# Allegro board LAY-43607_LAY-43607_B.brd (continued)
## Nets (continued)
GND: BH9.1 BH10.1 BT3.3 C5.2 C12.2 C14.2 C18.1 C20.2 C21.2 C22.2 C24.2 C25.2 C26.2 C27.2 C28.2 C30.2 C31.2 C32.2 C113.2 C114.2 C115.2 C116.2 C118.2 C119.2 C120.2 C125.2 C148.2 C149.2 C151.2 C152.2 C153.2 C155.2 C156.2 C157.2 C159.2 C160.2 C161.2 C162.2 C163.2 C164.2 C165.2 C166.2 C167.2 C168.2 C169.2 C170.2 C171.2 C172.2 C173.2 C174.2 C175.2 C176.2 C180.2 C181.2 C182.2 C183.2 C184.2 C185.2 C186.2 C187.2 C188.2 C189.2 C190.2 C191.2 C193.2 C194.2 C195.2 C196.2 C197.2 C198.2 C199.2 C200.2 C201.2 C202.2 C203.2 C204.2 C205.2 C206.2 C207.2 C208.2 C209.2 C210.2 C211.2 C212.2 C213.2 C214.2 C215.2 C216.2 C217.2 C218.2 C219.2 C220.2 C221.2 C222.2 C223.2 C224.2 C225.2 C226.2 C227.2 C228.2 C229.2 C230.2 C231.2 C232.2 C233.2 C234.2 C235.2 C236.2 C237.2 C238.2 C239.2 C240.2 C241.2 C242.2 C243.2 C244.2 C245.2 C246.2 C247.2 C248.2 C249.2 C252.2 C254.2 C258.2 C259.2 C260.2 C261.2 C262.2 C263.2 C264.2 C265.2 C266.2 C267.2 C268.2 C269.2 C270.2 C271.2 C275.2 C277.2 C278.2 C279.2 C280.2 C281.2 C282.2 C283.2 C284.2 C285.2 C286.2 C287.2 C288.2 C289.2 C290.2 C291.2 C292.2 C293.2 C294.2 C295.2 C296.2 C297.2 C298.2 C299.2 C300.2 C301.2 C302.2 C303.2 C304.2 C305.2 C306.2 C307.2 C308.2 C309.2 C310.2 C311.2 C312.2 C313.2 C314.2 C315.2 C316.2 C317.2 C318.2 C319.2 C320.2 C321.2 C322.2 C323.2 C324.2 C328.2 C329.2 C330.2 C332.2 C333.2 C334.2 C336.2 C337.2 C338.2 C364.2 C365.2 C366.2 C367.2 C369.2 C374.2 C375.2 C383.2 C384.2 C386.2 C388.2 C438.2 C449.2 C450.2 C451.2 C452.2 C453.2 C454.2 C457.2 C458.2 C459.2 C460.2 C487.2 C488.2 C489.2 C492.2 C493.2 C497.2 C498.2 C517.2 C518.2 C519.2 C520.2 C521.2 C522.2 C523.2 C524.2 C668.2 C669.2 C693.2 C729.2 C772.2 C787.2 C788.2 C789.2 C798.2 C851.2 C852.2 C853.2 C854.2 C855.2 C905.2 C933.2 C934.2 C935.2 C936.2 C1000.2 C1001.2 C1003.2 C1004.2 C1005.2 C1007.2 C1008.2 C1009.2 C1010.2 C1011.2 C1013.2 C1015.2 C1016.2 C1017.2 C1018.2 C1019.2 C1020.2 C1021.2 C1022.2 C1023.2 C1024.1 C1103.2 C1104.2 C1139.2 C1140.2 C1141.2 C1142.2 C1143.1 C1144.1 C1145.1 C1146.1 C1147.1 C1148.1 C1149.1 C1150.2 C1151.2 C1152.2 C1153.2 C1154.2 C1155.2 C1156.2 C1157.2 C1174.2 C1248.2 C1249.2 C1251.2 C1253.2 C1255.2 C1256.2 C1258.2 C1259.2 C1271.2 C1272.2 C1273.2 C1274.2 C1275.2 C1276.2 C1277.2 C1278.2 C1280.2 C1282.2 C1283.2 C1295.2 C1296.2 C1297.2 C1298.2 C1299.2 C1302.2 C1304.2 C1305.2 C1306.2 C1307.2 C1308.2 C1309.2 C1310.2 C1313.2 C1314.2 C1315.2 C1316.2 C1317.2 C1318.2 C1319.2 C1320.2 C1321.2 C1322.2 C1323.2 C1324.2 C1327.2 C1328.2 C1329.2 C1330.2 C1331.2 C1332.2 C1333.1 C1334.2 C1337.2 C1338.2 C1339.2 C1340.2 C1342.1 C1343.2 C1344.2 C1345.2 C1346.2 C1347.2 C1348.2 C1349.2 C1350.2 C1351.2 C1361.2 C1362.2 C1363.2 C1364.2 C1365.2 C1366.2 C1367.2 C1368.2 C1369.2 C1370.2 C1371.2 C1372.2 C1373.2 C1374.2 C1375.2 C1376.2 C1377.2 C1378.2 C1379.2 C1380.2 C1382.2 C1384.2 C1385.2 C1386.2 C1387.2 C1388.2 C1389.2 C1390.2 C1391.2 C1392.2 C1393.2 C1394.2 C1395.2 C1396.2 C1397.2 C1398.2 C1399.2 C1400.2 C1401.2 C1402.2 C1403.2 C1404.2 C1406.2 C1408.2 C1409.2 C1410.2 C1411.2 C1412.2 C1413.2 C1414.2 C1415.2 C1416.2 C1417.2 C1418.2 C1419.2 C1420.2 C1421.2 C1422.2 C1423.2 C1424.2 C1425.2 C1426.2 C1427.2 C1428.2 C1430.2 C1432.2 C1433.2 C1434.2 C1435.2 C1436.2 C1437.2 C1438.2 C1439.2 C1440.2 C1441.2 C1442.2 C1443.2 C1444.2 C1445.2 C1446.2 C1447.2 C1448.2 C1449.2 C1450.2 C1451.2 C1452.2 C1453.2 C1454.2 C1455.2 C1456.2 C1457.2 C1458.2 C1459.2 C1460.2 C1461.2 C1462.2 C1463.2 C1464.2 C1465.2 C1466.2 C1467.2 C1468.2 C1469.2 C1470.2 C1471.2 C1475.2 C1476.2 C1481.2 C1489.2 C1490.2 C1491.2 C1492.2 C1493.2 C1494.2 C1495.2 C1520.2 C1521.2 C1523.2 C1524.2 C1525.2 C1526.2 C1530.2 C1531.2 C1532.2 C1533.2 C1534.2 C1535.2 C1536.2 C1537.2 C1538.2 C1540.2 C1542.2 C1544.2 C1545.2 C1546.2 C1547.2 C1548.2 C1549.2 C1550.2 C1551.2 C1552.2 C1553.2 C1554.2 C1555.2 C1556.2 C1557.2 C1558.2 C1559.2 C1560.2 C1561.2 C1562.2 C1563.2 C1564.2 C1565.2 C1566.2 C1567.2 C1568.2 C1569.2 C1570.2 C1571.2 C1572.2 C1573.2 C1574.2 C1575.2 C1577.2 C1579.2 C1581.2 C1584.2 C1585.2 C1586.2 C1587.2 D4.C(CATHODE) D508.C(CATHODE) FL2.2A FL2.2B FL3.2 FL4.2 FL5.2 FL7.2 FL8.2 FL18.2 FL19.2 FL22.2 FL28.2 FL29.2 FL30.2 FL31.2A FL31.2B FL32.2A FL32.2B J13.1 J15.3 J15.5 J46.1 J46.7 J46.18 J46.33 J46.39 J46.45 J46.51 J46.57 J46.63 J46.69 J46.75 J52.1 J52.7 J52.18 J52.33 J52.39 J52.45 J52.51 J52.57 J52.63 J52.69 J52.75 J55.6(VSS) J56.8 J57.8 J58.5 J60.1 J63.2 J64.2 J65.2 J66.5 J67.7 J67.8 J67.13 J67.14 J70.4 J70.7 J70.13 J70.16 J73.4 J75.2 L2.3 L11.2 L514.2 P1.1 P1.20 P2.1 P2.20 Q4.1(SOURCE) R11.1 R33.2 R36.2 R64.2 R84.1 R100.2 R101.2 R102.2 R103.2 R104.2 R105.2 R106.2 R107.2 R141.1 R177.2 R185.2 R188.1 R192.2 R202.2 R228.2 R241.2 R242.2 R243.2 R248.2 R249.2 R257.2 R277.1 R412.2 R473.2 R474.2 R652.1 R653.1 R655.2 R661.2 R662.2 R745.2 R775.1 R776.1 R793.2 R812.1 R813.1 R817.2 R818.2 R823.2 R841.1 R850.2 R874.2 R875.2 R880.2 R881.2 R882.2 R883.2 R885.2 R886.2 R887.2 R902.2 R903.2 R907.2 R908.1 R909.1 R910.1 R911.1 R912.1 R913.1 R914.1 R915.1 R916.2 R917.2 R921.2 R930.2 R932.2 R933.2 R935.1 R943.2 R945.1 R955.2 R957.2 R959.2 R961.2 R963.2 R964.2 SW6.1 TP94.1 TP95.1 TVS1.2(A2) U1.3 U1.4 U1.7 U1.8 U1.14 U1.17 U14.A2 U14.A3 U14.A4 U14.A5 U14.A21 U14.AA4 U14.AA5 U14.AA7 U14.AA9 U14.AA12 U14.AA14 U14.AA17 U14.AA18 U14.AA19 U14.AA21 U14.AA24 U14.AB2 U14.AB7 U14.AB9 U14.AB12 U14.AB14 U14.AB17 U14.AB20 U14.AB26 U14.AC5 U14.AC6 U14.AC8 U14.AC10 U14.AC11 U14.AC15 U14.AC16 U14.AC18 U14.AC19 U14.AC21 U14.AC24 U14.AD2 U14.AD4 U14.AD5 U14.AD7 U14.AD9 U14.AD12 U14.AD14 U14.AD17 U14.AD20 U14.AD21 U14.AD26 U14.AE5 U14.AE7 U14.AE9 U14.AE12 U14.AE14 U14.AE17 U14.AE20 U14.AE21 U14.AE24 U14.AF4 U14.AF6 U14.AF7 U14.AF8 U14.AF9 U14.AF10 U14.AF11 U14.AF15 U14.AF16 U14.AF17 U14.AF18 U14.AF19 U14.AF21 U14.AF26 U14.AG1 U14.AG5 U14.AG6 U14.AG7 U14.AG8 U14.AG9 U14.AG11 U14.AG12 U14.AG13 U14.AG14 U14.AG15 U14.AG17 U14.AG18 U14.AG20 U14.AG21 U14.AG24 U14.AG26 U14.AH2 U14.AH5 U14.AH6 U14.AH7 U14.AH8 U14.AH9 U14.AH11 U14.AH12 U14.AH13 U14.AH14 U14.AH15 U14.AH17 U14.AH18 U14.AH20 U14.AH21 U14.B3 U14.B4 U14.B7 U14.B10 U14.B13 U14.B16 U14.B19 U14.B21 U14.B24 U14.B26 U14.C1 U14.C2 U14.C5 U14.C21 U14.C27 U14.D3 U14.D4 U14.D7 U14.D9 U14.D12 U14.D15 U14.D18 U14.D21 U14.D24 U14.E1 U14.E2 U14.E5 U14.E21 U14.E26 U14.F3 U14.F4 U14.F7 U14.F14 U14.F16 U14.F18 U14.F24 U14.G1 U14.G2 U14.G9 U14.G10 U14.G11 U14.G21 U14.G26 U14.H3 U14.H4 U14.H5 U14.H14 U14.H15 U14.H16 U14.H17 U14.H18 U14.H21 U14.H24 U14.J6 U14.J7 U14.J8 U14.J9 U14.J10 U14.J11 U14.J12 U14.J21 U14.J23 U14.J26 U14.K2 U14.K4 U14.K6 U14.K13 U14.K15 U14.K17 U14.K19 U14.K21 U14.L6 U14.L10 U14.L12 U14.L14 U14.L16 U14.L18 U14.L20 U14.L23 U14.L26 U14.M6 U14.M9 U14.M11 U14.M13 U14.M15 U14.M17 U14.M19 U14.M21 U14.M23 U14.N2 U14.N4 U14.N6 U14.N8 U14.N10 U14.N12 U14.N14 U14.N16 U14.N18 U14.N20 U14.N23 U14.N26 U14.P6 U14.P9 U14.P11 U14.P13 U14.P15 U14.P17 U14.P19 U14.P23 U14.R5 U14.R8 U14.R10 U14.R12 U14.R14 U14.R16 U14.R18 U14.R20 U14.R23 U14.R26 U14.T2 U14.T4 U14.T5 U14.T6 U14.T9 U14.T11 U14.T13 U14.T15 U14.T17 U14.T19 U14.T21 U14.T23 U14.T26 U14.U4 U14.U6 U14.U8 U14.U10 U14.U12 U14.U14 U14.U16 U14.U18 U14.U20 U14.U23 U14.V2 U14.V4 U14.V6 U14.V9 U14.V11 U14.V13 U14.V15 U14.V17 U14.V19 U14.V21 U14.V23 U14.V26 U14.W12 U14.W18 U14.W20 U14.W22 U14.Y2 U14.Y5 U14.Y6 U14.Y7 U14.Y8 U14.Y9 U14.Y10 U14.Y13 U14.Y14 U14.Y15 U14.Y16 U14.Y21 U14.Y23 U14.Y26 U15.A2 U15.A8 U15.B2 U15.C9 U15.D2 U15.D8 U15.E1 U15.E3 U15.E8 U15.E9 U15.F1 U15.G8 U15.H1 U15.H9 U15.K1 U15.K9 U15.M9 U15.N1 U15.N9 U15.T1 U16.A2 U16.A8 U16.B2 U16.C9 U16.D2 U16.D8 U16.E1 U16.E3 U16.E8 U16.E9 U16.F1 U16.G8 U16.H1 U16.H9 U16.K1 U16.K9 U16.M9 U16.N1 U16.N9 U16.T1 U17.A2 U17.A8 U17.B2 U17.C9 U17.D2 U17.D8 U17.E1 U17.E3 U17.E8 U17.E9 U17.F1 U17.G8 U17.H1 U17.H9 U17.K1 U17.K9 U17.M9 U17.N1 U17.N9 U17.T1 U18.A2 U18.A8 U18.B2 U18.C9 U18.D2 U18.D8 U18.E1 U18.E3 U18.E8 U18.E9 U18.F1 U18.G8 U18.H1 U18.H9 U18.K1 U18.K9 U18.M9 U18.N1 U18.N9 U18.T1 U24.2 U28.5 U35.4 U35.5 U36.4 U36.5 U37.4 U37.5 U37.6 U38.2(GND) U39.2(GND) U40.B3 U40.C3 U40.D3 U42.1 U44.3 U44.8 U50.41 U54.A2 U54.B2 U55.2 U56.3 U58.3 U60.3 U62.3 U114.3 U123.139(VSS_CASE) U123.D9 U522.C5 U522.F7 U522.K3 U522.K8 U523.2 U523.8(VSS) U524.1 U524.3 U524.4 U525.8(VSS) U527.3 U530.3 U532.10 U533.3 U534.3 U535.3 U536.3 U536.12 U536.21 U537.1 U538.4 U539.4 U539.5 U540.4 U540.5 U543.2(GND) U544.2(GND) U545.2(GND) U546.3 U547.3 U548.2 U549.4 U549.5 U550.B3 U550.C3 U550.D3 U551.3 U552.1 U553.3 U553.8 U554.3 U554.8 U555.4 U555.5 U555.6 U557.E1 U557.E2 U557.E5 U557.E6 U557.F1 U557.F2 U557.F5 U557.F6 U557.G1 U557.G2 U557.G5 U557.G6 U558.1 U558.2 U558.7 U560.3 U560.16 U560.25 U560.26 U560.27 U560.28 U561.12 U561.16 U561.19 U561.43 U561.45 U561.48 U561.51 U561.57 U562.3 U563.2(GND) U564.2(GND) U565.A2 U565.A8 U565.B2 U565.C9 U565.D2 U565.D8 U565.E1 U565.E3 U565.E8 U565.E9 U565.F1 U565.G8 U565.H1 U565.H9 U565.K1 U565.K9 U565.M9 U565.N1 U565.N9 U565.T1 U566.3
GND_EARTH: BH5.1 BH6.1 BH7.1 BH8.1 C386.1 C388.1 C1460.1 C1461.1 C1462.1 C1463.1 C1467.1 J55.SH1 J55.SH2 J55.SH3 J55.SH4 J58.S1 J58.S2 J58.S3 J58.S4(SHLD4) J70.S1 J70.S2 J70.S3 J70.S4 P1.S1 P1.S2 P1.S3 P1.S4 P2.S1 P2.S2 P2.S3 P2.S4 R202.1 R916.1 R917.1 R921.1
V1V0_GND: C36.2 C126.2 C127.2 C128.2 C1472.2 R15.2 R56.1 R887.1 U557.B5
V1V0_MS: R15.1 U557.B3
V1V0_RT: R56.2 U557.A3
V1V0_SVIN: C36.1 R13.2 U557.C1
V1V0_TRK: C1472.1 U557.B4
V3V3_BIAS: C1342.2 R904.2 U560.1
V3V3_COMP: C1471.1 R905.1 U560.22
V3V3_SW: L516.1 U560.8 U560.9 U560.10 U560.11 U560.12
V5V0_FB: C19.1 R7.1 R886.1 U1.13
V5V0_INTVCC: C1333.2 U1.2
V5V0_RT: R11.2 U1.1
V5V0_SS: C18.2 U1.15(TR/SS)
V5V0_SW: L515.1 U1.5 U1.6
VBAT: BT3.1 BT3.2(POS2) C1253.1 U523.19
VBUS: R849.1 R850.1 U536.8
VCC_USB1_PWR: C458.1 C459.1 C460.1 L11.1 U14.E7 U40.C2 U40.D1 U40.D2
VCC_USB2_PWR: C1321.1 C1322.1 C1323.1 L514.1 R255.1 R471.2 U550.C2 U550.D1 U550.D2
VDD_CLKOUT: C1436.1 C1437.1 C1438.1 C1439.1 C1440.1 C1441.1 C1442.1 FL30.1 U50.15 U50.18 U50.25 U50.28 U50.33
VDD_FB: C122.2 J8.1 R55.2 R59.1 U557.A5
VDD_FDIVH: C122.1 R52.2 R55.1 R894.1
VDD_FDIVL: R59.2 R60.2 R62.2 R64.1 R896.1
VDD_INTVCC: C125.1 U557.B6
VDD_ITH: C127.1 R67.1 U557.A4
VDD_LP: C163.1 J9.1 R144.1 R560.2 U14.G12
VDD_SEL: J8.2 R60.1
VDD_SI5332: C1273.1 C1274.1 C1275.1 C1276.1 C1277.1 FL28.1 U50.1 U50.4(VDD_XTAL) U50.9
VDD_SW: L9.1 U557.C3 U557.C4 U557.D3 U557.D4 U557.E3 U557.E4 U557.F3 U557.F4 U557.G3 U557.G4
VDD_VBUS: R899.1 U558.8
VDD_VOUTM: C126.1 R62.1 U557.A6(VOUTM)
VDDO7: C1278.1 FL29.1 U50.40
32KHZ_LP_RTC: R25.2 R33.1 U24.3
32KHZ_RTC: R36.1 R953.2 U24.1
BRD_REV0: R816.1 R817.1 U14.B18
BRD_REV1: R815.1 R818.1 U14.D17
BUFF_I2C1_SCL: J65.3 R856.2 U538.2
BUFF_I2C1_SDA: J65.1 R855.2 U538.7
C_USB1_TX_N: C463.1 J70.8 U553.1 U553.10(NC4)
C_USB1_TX_P: C464.1 J70.9 U553.2 U553.9
C_USB2_TX_N: C1326.2 J70.17 U553.5 U553.6
C_USB2_TX_P: C1325.2 J70.18 U553.4 U553.7
CFG_DRAM_TYPE: R228.1 U14.C11
CFG_ENG_USE0: R813.2 S1.10
CFG_RCW_SRC0: R908.2 S1.1
CFG_RCW_SRC1: R909.2 S1.2
CFG_RCW_SRC2: R910.2 S1.3
CFG_RCW_SRC3: R911.2 S1.4
CFG_RCW_SRC4: R912.2 S1.5
CFG_RCW_SRC5: R913.2 S1.6
CFG_RCW_SRC6: R914.2 S1.7
CFG_RCW_SRC7: R915.2 S1.8
CFG_RCW_SRC8: R812.2 S1.9
CLK_32KHZ: R25.1 R739.2 R953.1 U523.7
CLK_RTC: R143.2 U14.F17 U24.6
CLKGEN_OUT2_N: R792.1 U50.21
CLKGEN_OUT2_P: R791.1 U50.22
CLKGEN_OUT3_N: R788.1 U50.23
CLKGEN_OUT3_P: R787.1 U50.24
CLKGEN_OUT4_N: R790.1 U50.26
CLKGEN_OUT4_P: R789.1 U50.27
CLKGEN_OUT5_N: R786.1 U50.29
CLKGEN_OUT5_P: R785.1 U50.30
CLKGEN_OUT6_N: R784.1 U50.34
CLKGEN_OUT6_P: R783.1 U50.35
CLKGEN_OUT7: R781.1 U50.39
CLKGEN_OUT8: R782.1 U50.38
CONN_SPI_CLK: J66.4 U539.2
CONN_SPI_CS1_B: J66.6 U36.2
CONN_SPI_CS2_B: J66.7 U540.2
CONN_SPI_CS3_B: J66.8 U540.3
CONN_SPI_MISO: J66.3 R941.2
CONN_SPI_MOSI: J66.2 U35.2
CP2102_SIN: J72.2 U536.18
CP2102_SOUT: R837.2 R841.2 U536.17
CPU_ASLEEP: Q4.2 R192.1 U14.E9
CPU_CKSTP_OUT_B: R187.1 U14.G15
CPU_CLKOUT: TP126.1(PIN1) U14.G16
CPU_EVT0_B: R167.2 U14.E10
CPU_EVT1_B: R168.2 U14.E13
CPU_EVT2_B: R169.2 U14.E8
CPU_EVT3_B: R170.2 U14.E12
CPU_EVT4_B: R161.2 U14.E11
CPU_HRESET_B: R825.2 U14.F8 U114.2 U533.4(Y)
CPU_ID: R819.1 U14.AG3 U14.R4
CPU_JTAG_BSR_VSEL: R172.2 R185.1 U14.J19
CPU_JTAG_RST_B: J15.10(B5) R303.2 U55.1
CPU_JTAG_VTREF: J15.1 R186.2
CPU_LVDD: C330.1 C332.1 C333.1 C334.1 L56.2 U14.T7 U14.U7 U14.V7
CPU_PORESET_B: TP142.1(PIN1) U14.F9 U55.4(Y)
CPU_RESET_REQ_B: J14.2 U14.F10
CPU_SPI_PCS0: R861.2 U14.U1 U36.6
CPU_SPI_PCS1: R862.2 U14.R3 U36.7
CPU_SPI_PCS2: R860.2 U14.T3 U540.7
CPU_SPI_PCS3: R859.2 U14.V1 U540.6
CPU_SPI_SCK: U14.U2 U539.6 U539.7
CPU_SPI_SIN: U14.U3 U37.2
CPU_SPI_SOUT: U14.V3 U35.6 U35.7
CPU_SVDD: C254.1 C258.1 C259.1 C260.1 C261.1 C262.1 C263.1 C264.1 C265.1 FL7.1 R260.2 R261.2 U14.W10 U14.W13 U14.W14 U14.W15 U14.W16 U14.Y17 U14.Y18 U14.Y19
CPU_TBSCAN_EN_B: R171.2 R177.1 U14.F19
CPU_TCK: J15.4 R355.2 U14.E18
CPU_TDI: J15.8 U14.G17
CPU_TDO: J15.6 U14.E20
CPU_TMS: J15.2 U14.G18
CPU_TRST_B: R305.2 U14.E19 U56.4(Y)
CPU_USB_HVDD: C156.1 C157.1 C159.1 FL5.3(OUT_IN) U14.K8 U14.L8
CPU_USB_SDVDD: C152.1 C153.1 C155.1 FL4.3(OUT_IN) U14.M7 U14.M8
CPU_USB_SVDD: C148.1 C149.1 C151.1 FL3.3(OUT_IN) U14.K7 U14.L7
CPU_VDD: C162.1 C164.1 C165.1 C166.1 C167.1 C168.1 C169.1 C170.1 C171.1 C172.1 C173.1 C174.1 C175.1 C176.1 C180.1 C181.1 C182.1 C183.1 C184.1 C185.1 C186.1 C187.1 C188.1 C189.1 C190.1 C191.1 C193.1 C194.1 C195.1 C196.1 C197.1 C198.1 C199.1 C200.1 C201.1 C202.1 C203.1 C204.1 C205.1 C206.1 C207.1 C208.1 C209.1 C210.1 C211.1 C212.1 C213.1 C214.1 C215.1 C216.1 C217.1 C218.1 C219.1 C220.1 C221.1 C222.1 C223.1 C224.1 C225.1 C226.1 C227.1 C228.1 C229.1 C252.1 FL3.1 FL4.1 FL7.3(OUT_IN) J9.2 J12.1 R890.4(I2) U14.K14 U14.K16 U14.K18 U14.K20 U14.L11 U14.L13 U14.L15 U14.L17 U14.L19 U14.M10 U14.M12 U14.M14 U14.M16 U14.M18 U14.N9 U14.N11 U14.N13 U14.N15 U14.N17 U14.N19 U14.P10 U14.P12 U14.P14 U14.P16 U14.P18 U14.R9 U14.R11 U14.R13 U14.R15 U14.R17 U14.R19 U14.T10 U14.T12 U14.T14 U14.T16 U14.T18 U14.U9 U14.U11 U14.U13 U14.U15 U14.U17 U14.U19 U14.V10 U14.V12 U14.V14 U14.V16 U14.V18 U14.V20 U14.W11 U14.W17 U14.W19
CPU_VDD_I: C113.1 C114.1 C115.1 C116.1 C118.1 C119.1 C120.1 L9.2 R52.1 R890.1
CPU_XVDD: C266.1 C267.1 C268.1 C269.1 C270.1 C271.1 C275.1 FL8.3(OUT_IN) R92.2 R94.2 R96.2 R98.2 R258.2 R259.2 U14.AC7 U14.AC9 U14.AC12 U14.AC14 U14.AC17 U14.AC20
D1_ALERT_B: R142.2 U14.F28 U15.P9 U16.P9 U17.P9 U18.P9 U565.P9
D1_MA0: R111.1 U14.V27 U15.P3 U16.P3 U17.P3 U18.P3 U565.P3
D1_MA1: R113.1 U14.N27 U15.P7 U16.P7 U17.P7 U18.P7 U565.P7
D1_MA2: R112.1 U14.N28 U15.R3 U16.R3 U17.R3 U18.R3 U565.R3
D1_MA3: R115.1 U14.M28 U15.N7 U16.N7 U17.N7 U18.N7 U565.N7
D1_MA4: R114.1 U14.L28 U15.N3 U16.N3 U17.N3 U18.N3 U565.N3
D1_MA5: R117.1 U14.L27 U15.P8 U16.P8 U17.P8 U18.P8 U565.P8
D1_MA6: R116.1 U14.K28 U15.P2 U16.P2 U17.P2 U18.P2 U565.P2
D1_MA7: R119.1 U14.J27 U15.R8 U16.R8 U17.R8 U18.R8 U565.R8
D1_MA8: R118.1 U14.J28 U15.R2 U16.R2 U17.R2 U18.R2 U565.R2
D1_MA9: R121.1 U14.G28 U15.R7 U16.R7 U17.R7 U18.R7 U565.R7
D1_MA10: R120.1 U14.Y28 U15.M3 U16.M3 U17.M3 U18.M3 U565.M3
D1_MA11: R123.1 U14.H28 U15.T2 U16.T2 U17.T2 U18.T2 U565.T2
D1_MA12: R122.1 U14.G27 U15.M7 U16.M7 U17.M7 U18.M7 U565.M7
D1_MA13: R124.1 U14.AD27 U15.T8 U16.T8 U17.T8 U18.T8 U565.T8
D1_MACT_B: R133.1 U14.D28 U15.L3 U16.L3 U17.L3 U18.L3 U565.L3
D1_MBA0: R129.1 U14.Y27 U15.N2 U16.N2 U17.N2 U18.N2 U565.N2
D1_MBA1: R128.1 U14.W28 U15.N8 U16.N8 U17.N8 U18.N8 U565.N8
D1_MBG0: R130.1 U14.E27 U15.M2 U16.M2 U17.M2 U18.M2 U565.M2
D1_MBG1: R132.1 U14.E28
D1_MCAS_B: R125.1 U14.AC28 U15.M8 U16.M8 U17.M8 U18.M8 U565.M8
D1_MCKE0: R131.1 U14.C28 U15.K2 U16.K2 U17.K2 U18.K2 U565.K2
D1_MCLK0_N: R137.1 U14.R27 U15.K8 U16.K8 U17.K8 U18.K8 U565.K8
D1_MCLK0_P: R138.1 U14.R28 U15.K7 U16.K7 U17.K7 U18.K7 U565.K7
D1_MCS_B0: R136.1 U14.AB27 U15.L7 U16.L7 U17.L7 U18.L7 U565.L7
D1_MDIC_0: R141.2 U14.P28
D1_MDIC_1: R140.2 U14.U28
D1_MDM0: U14.B23 U15.E7
D1_MDM1: U14.H22 U15.E2
D1_MDM2: U14.E25 U16.E7
D1_MDM3: U14.J25 U16.E2
D1_MDM4: U14.V25 U17.E7
D1_MDM5: U14.AD24 U17.E2
D1_MDM6: U14.AC23 U18.E7
D1_MDM7: U14.AH24 U18.E2
D1_MDM8: U14.P24 U565.E7
D1_MDQ0: U14.C22 U15.G2
D1_MDQ1: U14.A23 U15.F7
D1_MDQ2: U14.C26 U15.H3
D1_MDQ3: U14.A27 U15.H7
D1_MDQ4: U14.B22 U15.H2
D1_MDQ5: U14.A22 U15.H8
D1_MDQ6: U14.B25 U15.J3
D1_MDQ7: U14.A26 U15.J7
D1_MDQ8: U14.E22 U15.A3
D1_MDQ9: U14.D22 U15.B8
D1_MDQ10: U14.F23 U15.C3
D1_MDQ11: U14.G23 U15.C7
D1_MDQ12: U14.G22 U15.C2
D1_MDQ13: U14.F22 U15.C8
D1_MDQ14: U14.C24 U15.D3
D1_MDQ15: U14.E23 U15.D7
D1_MDQ16: U14.D26 U16.G2
D1_MDQ17: U14.E24 U16.F7
D1_MDQ18: U14.G24 U16.H3
D1_MDQ19: U14.H25 U16.H7
D1_MDQ20: U14.C25 U16.H2
D1_MDQ21: U14.D25 U16.H8
D1_MDQ22: U14.G25 U16.J3
D1_MDQ23: U14.H26 U16.J7
D1_MDQ24: U14.K23 U16.A3
D1_MDQ25: U14.J24 U16.B8
D1_MDQ26: U14.L24 U16.C3
D1_MDQ27: U14.M24 U16.C7
D1_MDQ28: U14.J22 U16.C2
D1_MDQ29: U14.H23 U16.C8
D1_MDQ30: U14.K24 U16.D3
D1_MDQ31: U14.L25 U16.D7
D1_MDQ32: U14.V24 U17.G2
D1_MDQ33: U14.U26 U17.F7
D1_MDQ34: U14.AA26 U17.H3
D1_MDQ35: U14.W23 U17.H7
D1_MDQ36: U14.U24 U17.H2
D1_MDQ37: U14.U25 U17.H8
D1_MDQ38: U14.W24 U17.J3
D1_MDQ39: U14.Y25 U17.J7
D1_MDQ40: U14.AB24 U17.A3
D1_MDQ41: U14.AB25 U17.B8
D1_MDQ42: U14.AE25 U17.C3
D1_MDQ43: U14.AF25 U17.C7
D1_MDQ44: U14.Y24 U17.C2
D1_MDQ45: U14.AA25 U17.C8
D1_MDQ46: U14.AD25 U17.D3
D1_MDQ47: U14.AE26 U17.D7
D1_MDQ48: U14.AA22 U18.G2
D1_MDQ49: U14.AB23 U18.F7
D1_MDQ50: U14.AC22 U18.H3
D1_MDQ51: U14.AB22 U18.H7
D1_MDQ52: U14.Y22 U18.H2
D1_MDQ53: U14.AA23 U18.H8
D1_MDQ54: U14.AD22 U18.J3
D1_MDQ55: U14.AE22 U18.J7
D1_MDQ56: U14.AH25 U18.A3
D1_MDQ57: U14.AF24 U18.B8
D1_MDQ58: U14.AG22 U18.C3
D1_MDQ59: U14.AF22 U18.C7
D1_MDQ60: U14.AH26 U18.C2
D1_MDQ61: U14.AG25 U18.C8
D1_MDQ62: U14.AF23 U18.D3
D1_MDQ63: U14.AH22 U18.D7
D1_MDQS0_N: U14.A24 U15.F3
D1_MDQS0_P: U14.A25 U15.G3
D1_MDQS1_N: U14.C23 U15.A7
D1_MDQS1_P: U14.D23 U15.B7
D1_MDQS2_N: U14.F26 U16.F3
D1_MDQS2_P: U14.F25 U16.G3
D1_MDQS3_N: U14.K25 U16.A7
D1_MDQS3_P: U14.K26 U16.B7
D1_MDQS4_N: U14.W25 U17.F3
D1_MDQS4_P: U14.W26 U17.G3
D1_MDQS5_N: U14.AC26 U17.A7
D1_MDQS5_P: U14.AC25 U17.B7
D1_MDQS6_N: U14.AD23 U18.F3
D1_MDQS6_P: U14.AE23 U18.G3
D1_MDQS7_N: U14.AG23 U18.A7
D1_MDQS7_P: U14.AH23 U18.B7
D1_MDQS8_N: U14.P26 U565.F3
D1_MDQS8_P: U14.P25 U565.G3
D1_MECC0: U14.M26 U565.G2
D1_MECC1: U14.N25 U565.F7
D1_MECC2: U14.T25 U565.H3
D1_MECC3: U14.T24 U565.H7
D1_MECC4: U14.M25 U565.H2
D1_MECC5: U14.N24 U565.H8
D1_MECC6: U14.R25 U565.J3
D1_MECC7: U14.R24 U565.J7
D1_MODT0: R135.1 U14.AD28 U15.K3 U16.K3 U17.K3 U18.K3 U565.K3
D1_MRAS_B: R127.1 U14.AA28 U15.L8 U16.L8 U17.L8 U18.L8 U565.L8
D1_MWE_B: R126.1 U14.AB28 U15.L2 U16.L2 U17.L2 U18.L2 U565.L2
D1_PAROUT: R134.1 U14.V28 U15.T3 U16.T3 U17.T3 U18.T3 U565.T3
DDR4_CLK_TERM: C431.2 R137.2 R138.2
DDR4_ZQ0: R105.1 U17.F9(ZQ)
DDR4_ZQ1: R106.1 U18.F9(ZQ)
DDR4_ZQ2: R103.1 U15.F9(ZQ)
DDR4_ZQ3: R104.1 U16.F9(ZQ)
DDR4_ZQ5: R107.1 U565.F9(ZQ)
DDR_CLK_100MHZ_LVCMOS: R782.2 U14.J20
DDR_VREF1: C1406.1 R960.2 R961.1 U15.M1
DDR_VREF2: C1430.1 R962.2 R963.1 U16.M1
DDR_VREF3: C669.1 R954.2 R955.1 U17.M1
DDR_VREF4: C1382.1 R956.2 R957.1 U18.M1
DDR_VREF5: C1577.1 R958.2 R959.1 U565.M1
DDR_VTT: C402.1 C403.1 C408.1 C409.1 C410.1 C1352.1 C1353.1 C1354.1 C1355.1 C1356.1 C1357.1 C1358.1 C1359.1 C1360.1 C1533.1 C1534.1 C1535.1 C1584.1 C1585.1 L536.1 R111.2 R112.2 R113.2 R114.2 R115.2 R116.2 R117.2 R118.2 R119.2 R120.2 R121.2 R122.2 R123.2 R124.2 R125.2 R126.2 R127.2 R128.2 R129.2 R130.2 R131.2 R132.2 R133.2 R134.2 R135.2 R136.2 U561.30
DIFF_SYSCLK_N: R863.2 U14.AB13 U50.16
DIFF_SYSCLK_P: R863.1 U14.AA13 U50.17
EMI2_MDC: R870.2 R872.1 U123.C11
EMI2_MDIO: R871.1 U14.AH3 U123.D10
FA_VL: C337.1 C338.1 J12.2 R102.1 U14.AB21 U14.U5
FTM7_CH0: U14.A19 U548.5
FUSE_PWR_STATUS#: R948.2 U566.4(Y)
GPIO3_02: J67.6 U14.Y3 U543.4
GPIO3_03: J67.10 U14.Y4 U544.1
GPIO3_04: J67.4 U14.AA3 U543.3
GPIO3_05: J67.5 U14.AB3 U543.5
GPIO3_06: J67.2 U14.AB4 U543.1
GPIO3_07: J67.12 U14.W4 U544.3
GPIO3_08: J67.9 U14.AC3 U544.7
GPIO3_09: J67.20 U14.W2 U545.4
GPIO3_10: J67.16 U14.Y1 U545.1
GPIO3_11: J67.1 U14.AA1 U543.7
GPIO3_12: J67.3 U14.AA2 U543.6
GPIO3_13: J67.18 U14.W1 U545.3
GPIO3_14: J67.11 U14.AB1 U544.6
GPIO3_15: J67.15 U14.AD3 U545.7
GPIO3_16: J67.17 U14.AE3 U545.6
GPIO3_17: J67.19 U14.AE4 U545.5
GPIO3_21: U14.AG4 U548.4
GPIO_FUSE_PROG: R412.1 U14.AE1 U549.6
GVDD: C279.1 C280.1 C281.1 C282.1 C283.1 C284.1 C285.1 C286.1 C287.1 C288.1 C289.1 C303.1 C304.1 C305.1 C306.1 C307.1 C308.1 C309.1 C310.1 C311.1 C312.1 C313.1 C314.1 C315.1 C316.1 C317.1 C318.1 C319.1 C320.1 C321.1 C322.1 C323.1 C324.1 C364.1 C365.1 C366.1 C367.1 C374.1 C375.1 C383.1 C384.1 C402.2 C403.2 C408.2 C409.2 C410.2 C431.1 C517.1 C518.1 C519.1 C520.1 C521.1 C522.1 C523.1 C524.1 C668.1 C1349.1 C1350.1 C1351.1 C1352.2 C1353.2 C1354.2 C1355.2 C1356.2 C1357.2 C1358.2 C1359.2 C1360.2 C1361.1 C1362.1 C1363.1 C1364.1 C1365.1 C1366.1 C1367.1 C1368.1 C1369.1 C1370.1 C1371.1 C1372.1 C1373.1 C1374.1 C1375.1 C1376.1 C1377.1 C1378.1 C1379.1 C1380.1 C1385.1 C1386.1 C1387.1 C1388.1 C1389.1 C1390.1 C1391.1 C1392.1 C1393.1 C1394.1 C1395.1 C1396.1 C1397.1 C1398.1 C1399.1 C1400.1 C1401.1 C1402.1 C1403.1 C1404.1 C1409.1 C1410.1 C1411.1 C1412.1 C1413.1 C1414.1 C1415.1 C1416.1 C1417.1 C1418.1 C1419.1 C1420.1 C1421.1 C1422.1 C1423.1 C1424.1 C1425.1 C1426.1 C1427.1 C1428.1 C1530.1 C1531.1 C1532.1 C1556.1 C1557.1 C1558.1 C1559.1 C1560.1 C1561.1 C1562.1 C1563.1 C1564.1 C1565.1 C1566.1 C1567.1 C1568.1 C1569.1 C1570.1 C1571.1 C1572.1 C1573.1 C1574.1 C1575.1 C1586.1 L535.1 R82.1 R83.1 R140.1 R142.1 R558.1 R954.1 R956.1 R958.1 R960.1 R962.1 U14.AA27 U14.AC27 U14.AE27 U14.AG27 U14.AH27 U14.B27 U14.D27 U14.F27 U14.H27 U14.K27 U14.L22 U14.M22 U14.M27 U14.N22 U14.P22 U14.P27 U14.R22 U14.T22 U14.U22 U14.U27 U14.V22 U14.W27 U15.A1 U15.A9 U15.B3 U15.B9 U15.C1 U15.D1 U15.D9 U15.F2 U15.F8 U15.G1 U15.G7 U15.G9 U15.J1 U15.J2 U15.J8 U15.J9 U15.L1 U15.L9 U15.R1 U15.T9 U16.A1 U16.A9 U16.B3 U16.B9 U16.C1 U16.D1 U16.D9 U16.F2 U16.F8 U16.G1 U16.G7 U16.G9 U16.J1 U16.J2 U16.J8 U16.J9 U16.L1 U16.L9 U16.R1 U16.T9 U17.A1 U17.A9 U17.B3 U17.B9 U17.C1 U17.D1 U17.D9 U17.F2 U17.F8 U17.G1 U17.G7 U17.G9 U17.J1 U17.J2 U17.J8 U17.J9 U17.L1 U17.L9 U17.R1 U17.T9 U18.A1 U18.A9 U18.B3 U18.B9 U18.C1 U18.D1 U18.D9 U18.F2 U18.F8 U18.G1 U18.G7 U18.G9 U18.J1 U18.J2 U18.J8 U18.J9 U18.L1 U18.L9 U18.R1 U18.T9 U561.31 U565.A1 U565.A9 U565.B3 U565.B9 U565.C1 U565.D1 U565.D9 U565.F2 U565.F8 U565.G1 U565.G7 U565.G9 U565.J1 U565.J2 U565.J8 U565.J9 U565.L1 U565.L9 U565.R1 U565.T9
I2C1_CH0_SCL: R750.2 U28.8 U523.1 U524.6 U525.5 U558.5 U561.55
I2C1_CH0_SDA: R751.2 U28.7 U523.4 U524.5 U525.4 U558.4 U561.56
I2C1_M2CARD1_SCL: J46.60 R756.2 U525.7
I2C1_M2CARD1_SDA: J46.58 R757.2 U525.6
I2C1_M2CARD2_SCL: J52.60 R754.2 U525.10
I2C1_M2CARD2_SDA: J52.58 R755.2 U525.9
I2C1_SCL: R749.2 U14.N1 U525.14 U538.3
I2C1_SDA: R748.2 U14.M1 U525.15 U538.6
I2C1_UBUS_SCL: J57.5 R752.2 U525.12
I2C1_UBUS_SDA: J57.6 R753.2 U525.11
I2C3_SCL: J64.3 R854.2 U554.4
I2C3_SDA: J64.1 R853.2 U554.5
I2C3_USB2_SEL: U554.10 U555.2
I2C3_USB2_SEL_IO: R885.1 U14.AD1 U555.7
I2C4_SCL: J63.3 R852.2 U14.M3
I2C4_SDA: J63.1 R851.2 U14.N3
I2C_ADDR_A0: R277.2 U50.10
IFC_AD0: U14.B8 U522.J8
IFC_AD1: U14.A8 U522.K7
IFC_AD2: U14.B9 U522.J7
IFC_AD3: U14.A9 U522.K6
IFC_AD4: U14.A10 U522.K5
IFC_AD5: U14.B11 U522.K4
IFC_AD6: U14.A11 U522.J4
IFC_AD7: U14.B12 U522.H4
IFC_AD8: S1.20 U14.A12
IFC_AD9: S1.19 U14.A13
IFC_AD10: S1.18 U14.B14
IFC_AD11: S1.17 U14.A14
IFC_AD12: S1.16 U14.B15
IFC_AD13: S1.15 U14.A15
IFC_AD14: S1.14 U14.A16
IFC_AD15: S1.13 U14.A17
IFC_AVD: R873.1 U14.A18 U522.C4
IFC_CLE: S1.12(B9) U14.C19 U522.D5
IFC_OE_B: R203.2 U14.C18 U522.D4
IFC_RB0_B: R204.2 U14.C16 U522.C8
IFC_RB1_B: R205.2 U14.D16
IFC_TE: R814.1 U14.E14
IFC_WE_B: S1.11 U14.C15 U522.C7
IFC_WP_B: U14.D19 U522.C3
INA_VDD_S_N: C1335.2 R889.2 U558.9(VIN-)
INA_VDD_S_P: C1335.1 R888.1 U558.10
INTVCC: U560.2
IRQ_RTC_B: R742.1 U14.J5 U523.17
LED_ASLEEP: D2.C(CATHODE) R191.2
LP_TMP_DETECT_B: R560.1 U14.H12
LS1043A_GND_SENSE: R897.2 U14.W5
LS1043A_VDD_SENSE: R893.2 U14.V5
LS1046A_GND_SENSE: R898.2 U14.G20
LS1046A_VDD_SENSE: R895.2 U14.G19
M2_1_REFCLK_EN#: R775.2 R798.1 U50.19
M2_1_REFCLK_N: J46.49 R788.2
M2_1_REFCLK_P: J46.47 R787.2
M2_2_REFCLK_EN#: R776.2 R806.1 U50.20
M2_2_REFCLK_N: J52.49 R786.2
M2_2_REFCLK_P: J52.47 R785.2
MR_B: R302.2 U54.C1 U534.4(Y)
NAND_CS_B: R737.2 U14.C17 U522.C6
OUT6_OE_B: R945.2 R946.2 U50.31
OVDD: C290.1 C291.1 C292.1 C293.1 C294.1 C295.1 C296.1 C297.1 C336.1 C449.1 C451.1 C453.1 C487.1 C489.1 C492.1 C493.1 C497.1 C498.1 C905.1 C1248.1 C1249.1 C1251.1 C1295.1 C1296.1 C1297.1 C1306.1 C1308.1 C1314.1 C1317.1 C1318.1 C1328.1 C1433.1 C1520.1 C1521.1 C1523.1 FL29.3(OUT_IN) J11.2 J74.1 L56.1 L532.1 R91.1 R93.1 R95.1 R97.1 R143.1 R157.1 R158.2 R160.1 R161.1 R167.1 R168.1 R169.1 R170.1 R171.1 R172.1 R186.1 R187.2 R203.1 R204.1 R205.1 R298.1 R299.1 R301.1 R302.1 R303.1 R304.1 R305.1 R355.1 R656.1 R737.1 R809.1 R810.1 R811.1 R814.2 R815.2 R816.2 R819.2 R824.2 R825.1 R859.1 R860.1 R861.1 R862.1 R865.1 R866.1 R867.1 R868.1 R873.2 R947.1 U14.G8 U14.J14 U14.J15 U14.J16 U14.J17 U14.J18 U14.R7 U35.8(VCCB) U36.8(VCCB) U37.1 U55.5 U56.5 U58.5 U60.5 U62.5 U114.5 U522.D3 U522.G4 U522.H8 U522.J6 U527.5 U532.2 U533.5 U534.5 U539.8(VCCB) U540.8(VCCB) U546.5 U548.3 U548.6 U549.8(VCCB) U555.8(VCCB) U561.2
PEXM2_1_COEX1: J46.48 TP130.1(PIN1)
PEXM2_1_COEX2: J46.46 TP129.1(PIN1)
PEXM2_1_COEX3: J46.44 TP128.1(PIN1)
PEXM2_2_COEX1: J52.48 TP141.1(PIN1)
PEXM2_2_COEX2: J52.46 TP140.1(PIN1)
PEXM2_2_COEX3: J52.44 TP139.1(PIN1)
PEXM2_CLKREQ: J46.53 R668.2 R798.2
PEXM2_CLKREQ2: J52.53 R805.2 R806.2
PEXM2_LED1: D510.C(CATHODE) J46.6
PEXM2_LED2: D511.C(CATHODE) J52.6
PEXM2_PET1_N: C1168.1 J46.37
PEXM2_PET1_P: C1166.1 J46.35
PEXM2_PET2_N: C1294.1 J52.37
PEXM2_PET2_P: C1293.1 J52.35
PEXM2_WAKE2_B: J52.55 R804.2
PEXM2_WAKE_B: J46.55 R667.2
PMIC_EN: R927.2 U561.22
PMIC_FSOB: R936.2 U561.29
PMIC_INT_B: R929.2 U14.K5 U561.24
PMIC_LICELL: C1546.1 U561.46
PMIC_POR_B: R928.2 R939.1 U561.42
PMIC_RESET_MCU_B: R934.2 R938.1 U561.21
PMIC_STBY: R930.1 U561.23
PMIC_V1P5A: C1540.1 R937.1 U561.41
PMIC_V1P5D: C1545.1 U561.40
PMIC_VDDOTP: R933.1 U561.53
PORESET_B: R301.2 U54.C2 U55.3 U56.2 U58.2 U60.2 U62.2 U527.2 U532.3 U533.2 U546.2
PROG_SFP_EN: R409.2 U549.3 U566.2
PROG_SFP_Y_EN: Q3.1 R409.1
PS_3V3_PG: R6.1 R901.2 U560.23
PS_5V0_EN: R5.2 R6.2 U1.11
PS_V5V0_PG: R10.2 U1.12 U562.1
PS_VDD_EN: C1551.1 U557.B2 U561.28
PS_VDD_PG: R66.2 U557.A2 U562.2
PWR_PROG_MTR: C328.1 J11.1 R100.1 U14.F13
PWR_PROG_SFP: C329.1 J74.2 Q3.2(SOURCE) R101.1 U14.G13
QSG0_LED0: R645.1 U123.E2
QSG0_LED1: R646.1 U123.D1
QSG0_MDI0_N: P1.21 U123.D30
QSG0_MDI0_P: P1.15 U123.D31
QSG0_MDI1_N: P1.16 U123.C24
QSG0_MDI1_P: P1.23 U123.C25
QSG0_MDI2_N: P1.24 U123.C23
QSG0_MDI2_P: P1.18 U123.D29
QSG0_MDI3_N: P1.19 U123.C21
QSG0_MDI3_P: P1.26 U123.C22
QSG1_LED0: R643.1 U123.C3
QSG1_LED1: R644.1 U123.B2
QSG1_MDI0_N: P1.13 U123.B17
QSG1_MDI0_P: P1.6 U123.B18
QSG1_MDI1_N: P1.5 U123.C28
QSG1_MDI1_P: P1.11 U123.C29
QSG1_MDI2_N: P1.10 U123.B15
QSG1_MDI2_P: P1.3 U123.B16
QSG1_MDI3_N: P1.2(TRD4-) U123.C26
QSG1_MDI3_P: P1.8 U123.C27
QSG2_LED0: R647.1 U123.C5
QSG2_LED1: R648.1 U123.D5
QSG2_MDI0_N: P2.21 U123.C32
QSG2_MDI0_P: P2.15 U123.C33
QSG2_MDI1_N: P2.16 U123.B19
QSG2_MDI1_P: P2.23 U123.B20
QSG2_MDI2_N: P2.24 U123.A9
QSG2_MDI2_P: P2.18 U123.A10
QSG2_MDI3_N: P2.19 U123.C30
QSG2_MDI3_P: P2.26 U123.C31
QSG3_LED0: R649.1 U123.B4
QSG3_LED1: R650.1 U123.C6
QSG3_MDI0_N: P2.13 U123.C36
QSG3_MDI0_P: P2.6 U123.C1
QSG3_MDI1_N: P2.5 U123.D34
QSG3_MDI1_P: P2.11 U123.D35
QSG3_MDI2_N: P2.10 U123.C34
QSG3_MDI2_P: P2.3 U123.C35
QSG3_MDI3_N: P2.2(TRD4-) U123.D32
QSG3_MDI3_P: P2.8 U123.D33
QSGM_REXT: R662.1 U123.A8
QSGM_REXT0: R663.1 U123.D17
QSGM_REXT1: R663.2 U123.D18
QSGPHY1_INT_B: R656.2 R660.2 U14.F15
QSGPHY1_RST_B: R654.1 U62.4(Y) U123.B5
QSGPHY_REFCLK_125M_N: C850.1 U50.13
QSGPHY_REFCLK_125M_P: C849.1 U50.14
QSPI_A_CS0: R809.2 U14.D8 U532.7
QSPI_A_DATA0: U14.D11 U532.15
QSPI_A_DATA1: U14.C12 U532.8
QSPI_A_DATA2: R810.2 U14.D13 U532.9(W\/DQ2)
QSPI_A_DATA3: R811.2 U14.C13 U532.1
QSPI_A_SCK: U14.C9 U532.16
R_LED_ASLEEP: Q4.3 R191.1
R_USB1_LED: D4.A R244.2
R_USB2_LED: D508.A R879.2
RESET_MCU_B: R938.2 R939.2 U547.2
RESET_REQ_B: J14.1 R298.2 U534.2
RST_I2CMUX_B: R758.2 U525.3 U527.4(Y)
RST_MEM_B: R558.2 U15.P1 U16.P1 U17.P1 U18.P1 U114.4(Y) U565.P1
RSV_IO: R823.1 R824.1 U14.AF3
SCAN_MODE: R160.2 U14.H19
SD1_IMP_CAL_RX: R260.1 U14.Y11
SD1_IMP_CAL_TX: R258.1 U14.AA6
SD1_REFCLK2_N: R792.2 U14.AB8
SD1_REFCLK2_P: R791.2 U14.AA8
SD1_RX2_N: C1583.1 U123.D13
SD1_RX2_P: C1582.1 U123.D14
SD1_TX2_N: C848.1 U14.AE10
SD1_TX2_P: C847.1 U14.AD10
SD2_IMP_CAL_RX: R261.1 U14.Y12
SD2_IMP_CAL_TX: R259.1 U14.Y20
SD2_REFCLK1_N: R784.2 U14.AE13
SD2_REFCLK1_P: R783.2 U14.AD13
SD2_REFCLK2_N: R790.2 U14.AB19
SD2_REFCLK2_P: R789.2 U14.AB18
SD2_RX1_N: J46.43 U14.AH16
SD2_RX1_P: J46.41 U14.AG16
SD2_RX3_N: J52.43 U14.AH19
SD2_RX3_P: J52.41 U14.AG19
SD2_TX1_N: C1168.2 U14.AE16
SD2_TX1_P: C1166.2 U14.AD16
SD2_TX3_N: C1294.2 U14.AE19
SD2_TX3_P: C1293.2 U14.AD19
SD_CLK: J55.5 R239.2 R832.2 U39.1
SD_CMD: J55.3 R833.2 U14.P2 U38.4
SD_DATA0: J55.7 R828.2 U14.P1 U38.7
SD_DATA1: J55.8 R829.2 U14.R2 U38.1
SD_DATA2: J55.1 R830.2 U14.R1 U39.4
SD_DATA3: J55.2 R831.2 U14.T1 U39.5
SDHC_CD_B: J55.9 R834.2 U14.K3 U38.5
SDHC_WP: R241.1 U14.L3
SENSE_VDD: R893.1 R894.2 R895.1 R899.2
SENSE_VSS: R896.2 R897.1 R898.1
SI5332_SCL: R777.2 U50.11
SI5332_SDA: R778.2 U50.12
SLOT1_RST_B: J46.52 R666.2 U58.4(Y)
SLOT2_RST_B: J52.52 R803.2 U60.4(Y)
SOC_SD_CLK: R239.1 U14.P3
SPI_MISO: R941.1 R942.1 U37.7
SW1LX: L531.2 U561.5
SW2LX: L532.2 U561.6
SW3LX: L533.2 U561.9
SW5LX: L535.2 U561.33
SW6LX: L536.2 U561.34
SW7LX: L537.2 U561.36
SW_QSGPHY1_RST_B: R867.2 U14.AF1 U62.1
SW_RST: R299.2 SW6.2(SW2) U534.1
SW_SLOT1_RST_B: R865.2 U14.AC4 U58.1
SW_SLOT2_RST_B: R866.2 U14.AC1 U60.1
SW_UBUS1_RST: R868.2 U14.AE2 U546.1
SYS_CLK_100MHZ_LVCMOS: R781.2 U14.G14
SYS_PGOOD#: R924.2 U535.4(Y)
SYS_STATUS#: U14.E17 U549.7
SYS_STATUS_LT#: R925.2 U549.2
TA_BB_RTC: R144.2 U14.F12 U24.4
TDI_ANODE: C437.2 U14.J13 U28.2
TDI_CATHODE: C437.1 U14.H13 U28.3
TEST_SEL_B: J13.2 R157.2 U14.F20
THERM_FAULT_B: R743.1 U14.J4 U28.4
THERM_WARN_B: R744.1 U14.J3 U28.6
TMP_DETECT_B: R158.1 U14.H20
U25_IFS: U523.5 U523.18
UART1_SIN: J72.1 J73.3 U14.H2 U563.4
UART1_SOUT: J73.2 R837.1 U14.H1 U563.1
UART2_CTS_B: J60.6 U14.M2 U564.6
UART2_RTS_B: J60.2 U14.L1 U564.5
UART2_SIN: J60.4 U14.K1 U564.1
UART2_SOUT: J60.5 U14.L2 U564.4
UART_PWR2: J60.3 R920.2
UBUS1_AN: R401.1 U548.8
UBUS1_INT: J57.2 R869.2 U14.L5
UBUS1_PWM: J57.1 U548.1
UBUS1_RST: J56.2 R864.2 U546.4(Y)
UBUS1_SPI_CLK: J56.4 U539.3
UBUS1_SPI_CS0_B: J56.3 U36.3
UBUS1_SPI_MISO: J56.5 R942.2
UBUS1_SPI_MOSI: J56.6 U35.3
UBUS1_UART_SIN: J57.3 U14.J1
UBUS1_UART_SOUT: J57.4 U14.J2
USB1_DRVVBUS: R242.1 U14.H6 U40.A1
USB1_ID: R248.1 U14.F5
USB1_ILIM: R243.1 U40.A3
USB1_ISO_VOUT: C1280.1 J70.1 L11.3 R244.1 U42.4(VCC)
USB1_PWRFAULT: R793.1 U14.G6 U530.4(Y)
USB1_RESREF: R249.1 U14.G3
USB1_RX_N: J70.5 U14.E4 U44.4 U44.7
USB1_RX_P: J70.6 U14.E3 U44.5 U44.6
USB1_TX_N: C463.2 U14.F2
USB1_TX_P: C464.2 U14.F1
USB1_UDM: J70.2 U14.E6 U42.3
USB1_UDP: J70.3 U14.F6 U42.2
USB2_DRVVBUS: R882.1 U550.A1 U554.6
USB2_DRVVBUS_I2C3_SCL: U14.L4 U554.2
USB2_ID: R883.1 U14.D5
USB2_ILIM: R881.1 U550.A3
USB2_ISO_VOUT: C1324.1 J70.10(VBUS2) L514.3 R879.1 U552.4(VCC)
USB2_PWRFAULT: R880.1 U551.4(Y) U554.7
USB2_PWRFAULT_I2C3_SDA: U14.M4 U554.1
USB2_RESREF: R257.1 U14.G4
USB2_RX_N: J70.14 U14.C4 U44.2 U44.9
USB2_RX_P: J70.15 U14.C3 U44.1 U44.10(NC4)
USB2_TX_N: C1326.1 U14.D2
USB2_TX_P: C1325.1 U14.D1
USB2_UDM: J70.11 U14.C6 U552.3
USB2_UDP: J70.12 U14.D6 U552.2
USB2_VBUS: R255.2 U14.C7
USB3_ID: R473.1 U14.B5
USB3_RESREF: R474.1 U14.G5
USB3_VBUS: R471.1 U14.A7(USB3_VBUS)
USB_CONN_DM: J58.2 U536.5 U537.3
USB_CONN_DP: J58.3 U536.4 U537.2
USB_CONN_PWR: J58.1 R849.2 U537.4(VCC)
VSNVS: C1550.1 U561.47
N18041442: R304.2 U55.6 U535.2 U547.4(Y)
N26524532: R245.2 U40.A2 U530.2
N26564824: C847.2 U123.D16
N26564835: C848.2 U123.D15
N26564871: C849.2 U123.D11
N26564875: C850.2 U123.D12
N26565200: R651.2 R653.2 U123.B7
N26565210: R652.2 U123.B8
N26565245: R655.1 U123.D8
N26565259: R661.1 U123.C7
N26565267: C693.1 U123.A7
N26565570: R660.1 U123.C10
N26565580: R657.1 U123.C19
N26565586: R658.1 U123.B12
N26565592: R659.1 U123.D26
N26602439: C772.1 P1.7
N26602442: C1021.1 P1.12
N26602445: C1022.1 P1.4
N26602448: C1023.1 P1.9
N26631448: C1140.1 P1.31 R643.2
N26631451: C1139.1 P1.34 R644.2
N26631860: C1142.1 P1.27 R645.2
N26631884: C1141.1 P1.30 R646.2
N26633114: C1024.2 P1.14
N26633139: C1143.2 P1.22
N26633162: C1144.2 P1.17
N26633185: C1145.2 P1.25
N26633865: C1146.2 P2.14
N26633881: C1147.2 P2.22
N26633897: C1148.2 P2.17
N26633913: C1149.2 P2.25
N26633941: C1150.1 P2.27 R647.2
N26633965: C1151.1 P2.30 R648.2
N26634920: C1152.1 P2.7
N26634936: C1153.1 P2.12
N26634952: C1154.1 P2.4
N26634968: C1155.1 P2.9
N26634994: C1157.1 P2.31 R649.2
N26635018: C1156.1 P2.34 R650.2
N26645840: J46.56 R669.1
N26649122: D510.A R922.1
N26756957: TP127.1(PIN1) U523.6
N26760872: R745.1 U524.7(WP)
N26860199: J52.56 R801.1
N26860244: D511.A R923.1
N26874475: J15.9 R188.2
N26911462: J56.1 R401.2
N26937676: R857.2 U538.1
N26937874: R858.1 U538.5
N26987601: R870.1 U14.AH4
N27008437: R874.1 U14.AG2
N27008440: R875.1 U14.AF2
N27027375: R878.2 U550.A2 U551.2
N27121803: C128.1 R67.2
N27124315: R888.2 R890.2 TP116.1(PIN1)
N27124319: R889.1 R890.3 TP117.1(PIN1)
N27157188: C1341.2 R900.2 R902.1 U560.24
N27157490: R903.1 U560.18
N27163263: C1344.1 U560.21
N27259526: D509.1 R924.1
N27259549: D509.3 R925.1
N27260803: R940.2 U547.1 U562.4(Y)
N27955896: R931.1 U561.39
N27955915: R932.1 U561.52
N27960172: R935.2 U561.20
N27963255: C1552.1 U561.15
N27963260: C1553.1 U561.18
N27963345: C1554.1 U561.25
N27963673: R937.2 U561.44(XFAILB)
N28073320: R943.1 U561.14
N28144784: R944.2 U536.9
N28148907: R840.1 U536.13(WAKEUP)
N28150385: R843.2 U536.15
N28196038: R82.2 U565.E2
N28196089: R83.2 U565.A7
N28196104: R84.2 U565.B7
N28245014: D509.5 R948.1
N28345649: R964.1 U14.P21
N28397648: Q3.3 R947.2
N29074387: C1582.2 U14.AG10
N29074390: C1583.2 U14.AH10
N271624620: C1343.1 R905.2

Pads without a net: D509 7 8; J15 7; J46 3 5 8 9 10 11 12 13 14 15 16 17 19 20 21 22 23 32 34 36 38 40 42 50 54 59 61 62 64 65 66 67 68 70 71 73; J52 3 5 8 9 10 11 12 13 14 15 16 17 19 20 21 22 23 32 34 36 38 40 42 50 54 59 61 62 64 65 66 67 68 70 71 73; J58 4; U1 16; U14 A6 A20 AA10 AA15 AA20 AB5 AB10 AB11 AB16 AC2 AC13 AD6 AD8 AD11 AD15 AD18 AE6 AE8 AE11 AE15 AE18 AE28 AF5 AF12 AF13 AF14 AF20 AF27 AF28 AG28 B1 B2 B6 B17 B20 B28 C8 C10 C14 C20 D10 D14 D20 E15 E16 F11 F21 G7 H7 H8 K9 K10 K11 K12 K22 L9 L21 M5 M20 N5 N21 P4 P5 P8 P20 T8 T20 T27 T28 U21 V8 W3 W7 W8 W9 W21; U15 T7; U16 T7; U17 T7; U18 T7; U37 3; U38 3 6; U39 3 6 7; U50 2 3 5 6 7 8 32 36 37; U54 B1; U56 1; U114 1; U123 A1 A2 A3 A4 A5 A6 B1 B3 B6 B9 B10 B11 B13 B14 C2 C4 C8 C9 C12 C13 C14 C15 C16 C17 C18 C20 D2 D3 D4 D6 D7 D19 D20 D21 D22 D23 D24 D25 D27 D28; U522 A1 A2 A9 A10 B1 B9 B10 D6 D7 D8 E3 E4 E5 E6 E7 E8 F3 F4 F5 F6 F8 G3 G5 G6 G7 G8 H3 H5 H6 H7 J3 J5 L1 L2 L9 L10 M1 M2 M9 M10; U523 3 9 10 11 12 13 14 15 16; U527 1; U530 1; U532 4 5 6 11 12 13 14; U533 1; U535 1; U536 1 2 10 11 14 16 19 20; U544 4 5; U551 1; U555 3; U557 A1 B1; U558 3; U560 7 19 20; U561 1 10 49; U563 3 5 6 7; U564 3 7; U565 A3 B8 C2 C3 C7 C8 D3 D7 T7; U566 1

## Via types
v1: diameter 0.457, hole 0.206, TOP to BOTTOM, 571 vias
v2: diameter 0.457, hole 0.203, TOP to BOTTOM, 951 vias
v3: diameter 0.406, hole 0.203, TOP to BOTTOM, 198 vias
v4: diameter 0.508, hole 0.254, TOP to BOTTOM, 554 vias
v5: diameter 0.61, hole 0.305, TOP to BOTTOM, 450 vias
v6: diameter 0.45, hole 0.203, TOP to BOTTOM, 38 vias
v7: diameter 0.508, hole 0.257, TOP to BOTTOM, 87 vias

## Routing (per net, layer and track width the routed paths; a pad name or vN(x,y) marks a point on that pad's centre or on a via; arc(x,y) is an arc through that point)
1V0_F104: length 12
  TOP w0.137: v6(43.27,73.09) U123.E17 ; v6(40.67,73.09) U123.E13 ; v6(39.11,74.65) U123.E7 ; v6(44.82,75.3) U123.E23 ; v6(41.97,73.09) U123.E15 ; v2(37.11,72.63) 37.74,72.63 37.83,72.71 38.12,72.71 38.24,72.6 U123.E10 ; v6(44.82,74) U123.E21 ; v6(39.11,75.95) U123.E5 ; v6(44.72,72.6) U123.E19 ; v6(44.82,76.6) U123.E25
  TOP w0.254: U561.3 66.39,79.76 66.15,80.01 66.13,80.01 v4(65.64,80.49)
  BOTTOM w0.381: C855.1 38.98,75.95 v6(39.11,75.95) ; C853.1 41.97,72.37 v6(41.97,73.09) ; C852.1 37.11,72.19 v2(37.11,72.63) ; C854.1 38.26,74.32 38.58,74.65 v6(39.11,74.65)
  vias: v4(33.56,79.27) v4(33.64,78.33) v4(33.74,77.51) v4(34.28,78.03) v4(59.14,85.89) v4(59.14,85.18) v4(59.13,84.35) v4(59.13,83.64) v4(59.14,82.83) v4(60.11,84.4) v4(60.13,83.68)
1V0_QSG: length 9.3
  TOP w0.137: v2(38.42,71.98) 38.57,71.98 39.19,72.6 U123.E11
  TOP w0.254: v6(42.62,78.8) U123.E32 ; v6(41.32,73.09) U123.E14 ; v6(42.62,73.09) U123.E16 ; U123.E1 38.44,79.02 v6(38.44,78.45) ; v6(44.82,78.55) U123.E28 ; v6(41.32,78.8) U123.E34 ; v6(40.02,78.8) U123.E36 ; v6(43.92,78.8) U123.E30
  BOTTOM w0.203: C1003.1 38.44,79.73 v6(38.44,78.45)
  BOTTOM w0.381: C1005.1 42.62,72.7 v6(42.62,73.09) ; C1004.1 41.32,72.44 v6(41.32,73.09)
  vias: v4(33.46,82.06) v4(33.44,81.02) v4(33.49,84.88) v4(33.51,83.86) v4(33.49,83)
1V35: length 1.7
  TOP w0.254: U561.13 66.18,74.76 65.73,74.31 v4(65.39,74.31)
  vias: v4(42.13,50.38) v4(42.27,52.62) v4(42.51,51.8) v4(59.12,76.1) v4(59.16,74.17) v4(59.5,72.84) v4(60.14,76.19) v4(60.16,75.06)
2V5: length 89.7
  TOP w0.137: v6(44.82,77.25) U123.E26 ; v2(39.15,73.22) 39.02,73.35 U123.E9 ; v6(44.82,74.65) U123.E22 ; v6(40.02,73.09) U123.E12 ; v6(43.92,73.09) U123.E18 ; v6(44.82,75.95) U123.E24 ; v6(39.11,76.6) U123.E4 ; v6(39.11,75.3) U123.E6 ; v6(44.82,73.35) U123.E20 ; v6(39.11,74) U123.E8 ; v6(39.11,77.25) U123.E3
  TOP w0.254: v4(75.59,78.77) 75.58,78.76 U561.38
  TOP w0.381: 87.59,18.53 88.42,17.71 v2(89.24,17.71) ; U14.W6 v1(60.62,52.59) ; R654.2 v2(32.07,76.04) ; 76.24,18.31 76.83,17.71 v2(77.76,17.71) 77.04,16.98 76.44,16.98
  TOP w0.432: U15.B1 v2(89.24,17.71) ; U17.B1 v2(54.8,17.71) ; U18.B1 v2(43.32,17.71) ; U16.B1 v2(77.76,17.71) ; U16.R9 85.13,6.34 v2(85.13,5.45) ; U565.B1 v2(66.28,17.71)
  TOP w0.508: 75.72,17.65 76.39,16.98 76.44,16.98 ; 76.93,19.74 76.88,19.74 76.22,19.09 76.22,18.56 76.24,18.55 76.24,18.31 ; R871.2 v4(47.43,59.33) ; 87.49,18.64 87.55,18.57
  TOP w0.635: 87.55,18.57 87.59,18.53
  TOP w0.762: 77.12,19.93 85.09,19.93 86.38,18.64 87.49,18.64 ; 77.12,19.93 76.93,19.74 ; 77.12,19.93 77.09,19.96 73.42,19.96 ; 73.42,19.96 63.64,19.96 ; 73.42,19.96 75.72,17.65
  L3_INT_1 w0.381: 85.13,5.13 v2(85.13,5.45)
  L3_INT_1 w0.762: v5(85.13,2.84) 85.13,5.13
  BOTTOM w0.381: C1408.1 88.36,17.71 v2(89.24,17.71) ; C1015.1 44.21,72.24 43.9,72.55 43.92,72.56 v6(43.92,73.09) ; v6(44.82,73.35) 45.15,73.02 C1018.1 45.97,73.02 ; v1(73.08,6.91) 73.43,6.91 73.75,6.6 ; v6(44.82,74.65) 45.48,74.65 C1016.1 ; v6(44.82,75.95) 45.48,75.95 C1017.1 ; v2(77.76,17.71) 77.66,17.81 C1432.1 ; v2(43.32,17.71) 43.22,17.81 C1384.1 ; C1579.1 66.18,17.81 v2(66.28,17.71) ; 62.27,6.24 v1(61.6,6.91)
  BOTTOM w0.508: 97.27,6.7 97.06,6.91 v1(96.04,6.91) ; v2(54.8,17.71) 54,17.71 C369.1 ; v2(39.15,73.22) 39.03,73.22 38.78,73.47 C1019.1 ; 62.31,6.2 62.27,6.24 ; 74.04,6.3 73.75,6.6 ; v4(75.59,78.77) 75.59,79.35
  BOTTOM w0.762: 74.04,6.3 74.97,5.38 v4(74.97,2.84) ; 97.27,6.7 97.57,6.4 97.57,4.92 95.49,2.84 v5(85.13,2.84) ; v5(62.75,2.78) 62.75,5.76 62.31,6.2
  vias: v1(50.12,6.91) v2(35.77,21.86) v2(35.77,21.07) v2(36.43,21.86) v2(36.43,21.07) v2(37.35,21.84) v2(37.35,21.05) v2(38.01,21.84) v2(38.01,21.05) v4(28.41,89.73) v4(28.38,88.84) v4(29.65,89.7) v4(29.63,88.82) v4(49.24,75.1) v4(50.05,75.07) v4(50.43,86.3) v4(50.81,87.32) v4(50.79,85.26) v4(80.89,81.19) v4(81.53,80.2) v4(81.53,78.93) v4(82.55,81.6) v4(82.52,80.47) v4(82.5,79.27)
2V5_LED: length 96.3
  L3_INT_1 w0.508: P1.28 P1.29 46.91,119.75 37.81,119.75 35.2,117.14 P2.28 P2.29
  BOTTOM w0.508: P2.33 P2.32 35.35,92.28 39.62,92.28 40.92,90.99 41.26,90.99 FL22.3 ; P1.32 P1.33 50.4,89.88 48.12,89.88 46.85,91.15 46.02,91.15 45.39,90.52 C1104.1 43.75,90.52 C729.1 42.54,90.49 FL22.3 ; P2.28 35.2,112.2 37.42,109.97 38.57,109.97 42.15,106.39 FL22.3
2V5_QSG: length 5.9
  TOP w0.105: U123.E35 40.34,79.63 39.7,79.63 39.62,79.54 39.61,79.54 U123.E37
  TOP w0.137: U123.E27 45.61,78.19 45.61,78.32 45.66,78.38 45.66,78.8 45.16,79.3 U123.E29
  TOP w0.254: v6(40.67,78.8) U123.E35 ; v6(44.82,77.9) U123.E27 ; v6(43.27,78.8) U123.E31 ; v6(41.97,78.8) U123.E33
  vias: v4(50.53,81.42) v4(50.53,80.15) v4(50.53,79.14)
3V3: length 138.5
  TOP w0.254: U561.7 65.39,77.76 65.26,77.89 v4(65.26,77.91) ; U54.A1 118,20.2 ; U35.1 74.39,99.83 74.62,99.6 v2(74.62,99.59) ; U561.54 68.6,82.56 v4(68.57,82.59) ; U561.17 68.6,72.61 v4(68.53,72.54) ; v2(83.68,99.66) 83.59,99.66 83.28,99.97 U36.1 ; U540.1 86.28,100.02 86.59,99.71 v2(86.59,99.7) ; v4(100.82,77.84) 100.9,77.84 U554.9 ; U561.27 73.6,72.97 73.84,72.73 v4(73.84,72.67) ; v4(75.91,75.75) 75.9,75.76 U561.32 ; U525.16 86.92,90.84 86.73,90.64 v5(86.04,90.64) ; v4(76.23,78.27) 76.22,78.26 U561.37 74.4,78.26 74.06,77.93 74.06,77.6 74.4,77.26 U561.35 75.97,77.26 75.98,77.25 v4(76.49,77.25) ; v5(65.52,75.55) 65.73,75.76 U561.11 ; U561.8 66.22,77.26 66.2,77.24 v4(64.96,77.24) ; R928.1 v5(78.9,84.32) ; v2(75.47,99.61) 75.47,99.63 75.69,99.85 U37.8 ; U558.6 v2(127.37,56.01) ; v2(80.55,99.71) 80.49,99.71 80.19,100.02 U539.1 ; v4(73.14,72.43) 73.14,72.56 73.1,72.59 U561.26 ; v5(71,82.5) 71,82.33 70.6,81.93 U561.50 ; v5(65.92,79.45) 66.1,79.26 U561.4 ; v5(88.87,90.6) U525.13
  TOP w0.305: U551.5 102.64,88.95 v2(102.69,89) ; v4(120.07,15.1) 120.3,15.33 R843.1 121.63,15.33 R840.2 R944.1 ; v2(86.06,111.52) 86.17,111.63 U548.7
  TOP w0.381: v4(20.43,68.22) 20.68,67.97 R778.1 21.01,68.02 R777.1 ; U525.2 U525.1 86.92,86.67 86.78,86.82 v5(86.78,87.11) ; v2(86.06,111.52) 85.96,111.42 C1316.1 ; U562.5 120.05,27.86 C1555.1 v4(118.9,27.23) ; C1327.1 99.96,75.3 99.76,75.51 v4(99.12,75.51) ; v4(44.88,60.64) 44.88,60.66 R864.1 ; U14.N7 66.22,51.79 v1(66.23,51.79) ; U24.5 91.82,59.29 92.13,59.59 v4(92.13,59.59) ; R900.1 114.53,72.22 114.15,72.6 v4(114.15,72.64) 114.56,73.06 C1341.1 ; v1(65.43,51.79) 65.42,51.79 U14.P7 ; R10.1 v4(118.58,80.97) ; U530.5 101.31,85.15 v4(101.53,84.93) ; U14.R6 v1(63.83,52.59) ; 118,20.2 v4(117.49,20.2) 117.51,20.23 C488.1 ; U549.1 v4(100.33,64.82)
  TOP w0.508: R946.1 35.32,67.44 v4(34.9,67.86) ; 101.68,66.8 C1315.1 ; v5(35.47,46.77) 35.91,46.33 R922.2 ; R934.1 R927.1 v4(71.36,68.99) ; R744.2 100.41,62.01 100.49,61.93 v4(100.83,61.93) ; v5(24.98,76.48) 24.98,76.47 R742.2 ; D2.A 94.7,55.22 v5(94.35,55.58) ; v4(101.03,82.23) 100.85,82.41 U524.2 ; v4(105.07,62.39) 105.07,62.77 U538.8 ; v4(75.18,69) 75.3,69.11 R936.1 ; R667.1 v4(20.01,50.03) ; v5(28.35,72.66) 28.34,72.66 C1255.1 ; U28.1 v4(96.92,60.64) ; R668.1 v4(20.9,50.03) ; R739.1 v4(20.79,76.62) ; U524.8 v2(103.74,83.68) ; v4(49.84,56.91) C302.1
  L5_PWR w0.889: D509.6 118.27,114.04 ; D509.6 117.41,113.18 ; D509.6 118.27,112.31 ; D509.6 119.14,113.18 ; D509.2 119.14,108.1 ; D509.2 118.27,107.23 ; D509.2 118.27,108.96 ; D509.2 117.41,108.1 ; D509.4 119.14,110.64 ; D509.4 117.41,110.64 ; D509.4 118.27,109.77 ; D509.4 118.27,111.5 ; J66.1 66.41,89.72 ; J66.1 66.41,87.86 ; J66.1 67.33,88.79 ; J66.1 65.48,88.79 ; 68.2,99.34 J56.7 ; J56.7 70.23,99.34 ; J56.7 69.22,100.36 ; J56.7 69.22,98.33 ; J73.1 130.68,9.31 ; J73.1 129.75,8.39 ; J73.1 129.75,10.24 ; J73.1 128.83,9.31
  BOTTOM w0.254: C1547.1 74.03,72.89 73.85,72.71 73.85,72.69 v4(73.84,72.67) ; v4(73.14,72.43) C1548.1
  BOTTOM w0.305: v2(86.59,99.7) 86.58,99.71 C1309.1 ; C1307.1 80.43,99.59 v2(80.55,99.71) ; v2(74.62,99.59) 74.59,99.56 C450.1 ; v2(83.68,99.66) 83.6,99.59 C452.1 ; v2(75.47,99.61) 75.52,99.56 C454.1 ; v2(102.69,89) 102.69,88.14 R878.1
  BOTTOM w0.381: v4(118.58,80.97) 118.55,80.94 R5.1 ; v4(20.43,68.22) 20.58,68.37 FL28.3 ; U535.5 v4(100.3,70.9) ; U555.1 v4(99.12,75.51) ; C1319.1 v4(100.33,64.82) ; v4(101.53,84.93) R245.1 ; v4(100.82,77.84) 100.9,77.84 C278.1 ; U547.5 v4(102.42,66.8) ; v2(103.74,83.68) C1258.1
  BOTTOM w0.508: R901.1 113.46,72.7 113.51,72.64 v4(114.15,72.64) ; C1494.1 75.05,78.14 76.09,78.14 v4(76.23,78.27) ; v4(89.45,102.57) R753.1 90.22,102.57 R752.1 ; C1492.1 75.89,75.73 v4(75.91,75.75) ; R869.1 v5(89.47,113.05) ; C1334.1 127.76,56.41 v2(127.37,56.01) ; J73.1 129.6,9.16 C1466.1 ; C1313.1 69.1,99.46 J56.7 ; v5(86.78,87.11) 87.32,86.57 R758.1 ; R853.1 v5(106.11,72.65) ; v4(105.07,62.39) 105.07,63.06 C1305.1 ; C300.1 49.82,56.89 v4(49.84,56.91) ; R66.1 v5(127.62,54.5) ; R858.2 v5(104.16,66.04) ; C1256.1 v4(96.92,60.64) ; R851.1 v5(106.28,76.08) ; R929.1 71.7,69.17 71.54,69.17 v4(71.36,68.99) ; J66.1 66.56,88.94 C1310.1 ; FL5.1 v4(62.72,64.15) ; U523.20 v5(28.35,72.66) ; R749.1 R748.1 C1259.1 v5(86.04,90.64) ; v5(91.62,90.42) R755.1 R754.1 ; R854.1 v5(107.66,72.65) ; R852.1 v5(108.47,76.93) ; R904.1 v5(113.91,71.36)
  vias: v4(13.77,47.67) v4(13.82,46.61) v4(14.77,47.62) v4(14.8,46.61) v4(14.92,35.42) v4(14.92,34.33) v4(15.58,45.77) v4(15.89,33.7) v4(19.76,61.83) v4(19.86,65.6) v4(19.95,63.65) v4(20.32,69.19) v4(32.5,49.13) v4(32.92,50.19) v4(33.04,48.26) v4(33.32,36.09) v4(33.94,47.79) v4(34.25,35.32) v4(34.24,34.44) v4(34.71,47.79) v4(36.59,36.19) v4(37.86,36.29) v4(38.95,36.24) v4(111.83,61.08) v4(111.82,60.22) v4(111.82,58.82) v4(112.96,58.56) v4(114.23,58.56) v4(115.27,61.07) v4(115.25,60.09) v4(115.25,58.95) v4(116.06,60.98) v4(116.06,58.44) v4(117.46,60.98) v4(117.46,58.44) v4(118.86,60.98) v4(118.86,58.44) v4(120.13,60.98) v4(120.13,58.44) v4(121.27,58.44) v4(122.41,60.98) v4(122.41,59.96) v4(122.41,58.56) v4(123.56,58.31) v4(123.5,9.96) v4(123.54,9.05) v4(124.75,9.02) v4(124.83,58.31) v4(125.84,60.98) v4(125.84,59.83) v4(125.84,58.69) v4(127.62,60.98) v4(127.62,59.83) v4(127.62,58.69) v4(129.27,60.98) v4(129.27,59.83) v4(129.27,58.69) v5(78.22,119.19) v5(78.86,115.43) v5(79.16,119.17) v5(79.11,116.25) v5(126.04,26.72)
3V3_EN: length 6.3
  TOP w0.254: U560.17 121.18,69.86 121.75,70.43 121.75,71.8 120.99,72.56 120.99,72.69 120.99,72.69 R907.1 121,73.27 v2(121.85,73.27)
  BOTTOM w0.254: R906.2 v2(121.85,73.27)
5V0: length 13.4
  TOP w0.254: U550.B1 105.82,91.97 ; U550.B1 U550.B2 ; U550.B1 U550.C1 106.06,92.37 ; U40.B1 U40.C1 112.76,92.67 ; U40.B1 U40.B2 ; U40.B1 112.53,92.27 ; R7.2 118.23,81.83 118.64,82.25 v4(118.64,82.33) 118.64,82.57 118.39,82.82 C19.2
  L3_INT_1 w0.889: 92.08,98.33 J57.7 ; J57.7 92.08,100.36 ; J57.7 91.06,99.34 ; J57.7 93.09,99.34
  BOTTOM w0.508: J57.7 91.35,100.07 C1329.1
  vias: v5(105.78,88.66) v5(106.54,87.39) v5(106.54,86.25) v5(107.05,88.66) v5(107.73,87.65) v5(108.75,88.54) v5(108.75,87.65)
12V0: length 10.2
  TOP w0.889: 126.32,80.15 J75.1 ; J75.1 127.24,79.22 ; J75.1 127.24,81.08 ; J75.1 128.17,80.15
  L4_INT_2 w0.889: J75.1 127.24,81.08 ; J75.1 126.32,80.15 ; J75.1 127.24,79.22 ; J75.1 128.17,80.15
  BOTTOM w0.889: 126.32,80.15 J75.1 ; J75.1 127.24,81.08 ; J75.1 127.24,79.22
  vias: v5(116.6,98.26) v5(116.88,94.53) v5(116.93,92.37) v5(116.88,90.19) v5(118.12,98.21) v5(118.4,94.48) v5(118.45,92.32) v5(118.4,90.14) v5(119.64,98.21) v5(119.75,31.51) v5(119.75,30.5) v5(119.92,94.48) v5(119.92,90.14) v5(119.97,92.32) v5(121.24,98.21) v5(121.52,94.48) v5(121.52,90.14) v5(121.57,92.32) v5(121.91,80.79) v5(122.01,83.48) v5(122.29,31.51) v5(122.29,30.5) v5(122.62,92.83) v5(122.72,98.21) v5(122.69,91.69) v5(123.21,82.57) v5(123.18,81.42) v5(123.3,96.97) v5(123.3,95.67) v5(123.68,79.77) v5(123.81,78.76) v5(124.7,78.76) v5(125.08,33.16) v5(125.08,31.89) v5(125.08,30.62) v5(125.59,81.04) v5(125.59,79.77) v5(125.59,77.74) v5(126.22,78.5) v5(126.22,33.16) v5(126.22,31.89) v5(126.22,30.62) v5(127.24,33.16) v5(127.24,31.9) v5(127.24,30.62) v5(128.26,78.63) v5(128.56,77.84)
12V0_FILTERED_PS_V1V0: length 1.1
  BOTTOM w0.508: R13.1 120.87,48.93 v5(120.64,49.17)
  vias: v5(119.75,51.83) v5(119.94,48.5) v5(119.99,41.86) v5(120.38,39.01) v5(120.52,51.68) v5(120.76,50.18) v5(120.76,41.04) v5(120.76,39.9) v5(120.89,37.1) v5(122.03,37.1) v5(122.16,50.44) v5(122.16,49.29) v5(123.18,37.1) v5(124.32,37.1) v5(124.83,35.07) v5(124.95,36.09)
12V0_FILTERED_PS_V3V3: length 2.9
  TOP w0.254: U560.6 U560.5 U560.4 ; U560.13 U560.14 U560.15
  BOTTOM w0.508: R906.1 v5(120.98,75.18)
  vias: v4(113.16,67.64) v4(113.18,66.72) v4(114.15,66.44) v4(115.05,66.44) v4(115.5,66.96) v4(115.79,67.6) v4(122.66,67.5) v4(123.81,67.02) v4(124.39,67.89) v4(124.7,67.07) v4(125.4,68.21) v4(125.59,67.07) v4(126.73,67.07) v4(127.49,67.07) v4(128.38,67.07) v4(129,70.64) v4(129,69.71) v4(129,68.7) v4(129,67.8)
12V0_FILTERED_PS_V5V0:
  vias: v5(113.84,78.02) v5(115.83,79.65) v5(115.83,78.5) v5(116.7,79.65) v5(116.7,78.5)
12V0_IN: length 14.5
  TOP w0.889: J1.1 128.55,109.05 ; J1.1 123.42,109.05 ; J1.1 125.98,107.99 ; J1.1 125.98,110.1
  BOTTOM w0.889: J1.1 128.55,109.05 ; J1.1 123.42,109.05 ; J1.1 125.98,110.1 ; J1.1 125.98,107.99
  vias: v5(121.5,111.9) v5(121.47,110.3) v5(121.5,108.55) v5(123.94,111.93) v5(126.58,111.88) v5(127.19,107.13) v5(127.19,105.66) v5(128.64,111.85) v5(128.64,107.15) v5(128.69,105.63)
12V0_IN_GND: length 13.1
  TOP w0.889: J1.2 128.19,115.05 ; J1.2 125.98,113.99 ; J1.2 125.98,116.1 ; J1.2 123.77,115.05
  BOTTOM w0.889: J1.2 125.98,116.1 ; J1.2 128.19,115.05 ; J1.2 123.77,115.05 ; J1.2 125.98,113.99
  vias: v5(123.12,114.22) v5(123.25,116.15) v5(123.94,113.53) v5(124.27,116.76) v5(125.21,99.86) v5(126.63,101.92) v5(126.63,100.75) v5(127.26,99.84) v5(127.57,116.73) v5(127.52,104.06) v5(127.57,102.86) v5(127.95,113.48) v5(128.84,115.97) v5(128.81,114.01) v5(128.92,104.03) v5(128.92,102.56) v5(130.54,111.27) v5(130.59,109.52) v5(130.62,107.43) v5(130.62,105.58) v5(130.74,104.13) v5(130.8,102.56)
12V0_PS_F:
  vias: v5(115.68,105.45) v5(115.78,104.08) v5(115.78,102.63) v5(117.54,105.4) v5(117.51,104.06) v5(117.56,102.63) v5(119.34,105.35) v5(119.39,104) v5(119.49,102.63) v5(121.83,106.9) v5(121.83,105.48) v5(121.85,103.78) v5(121.85,102.33) v5(122.49,100.58)
AVDD_CGA1: length 3.2
  TOP w0.381: U14.H11 69.83,48.2 v1(70.23,48.59)
  BOTTOM w0.381: v4(78.2,49.68) C231.1 C230.1 R91.2
AVDD_CGA2: length 2.9
  TOP w0.381: U14.H10 69.82,49 v1(69.42,49.4)
  BOTTOM w0.381: C235.1 C236.1 R93.2 v4(78.26,45.81)
AVDD_DDR1: length 0.6
  TOP w0.381: U14.R21 64.22,40.2 v1(63.83,39.8)
  vias: v2(86.48,36.68)
AVDD_PLAT: length 3.2
  TOP w0.381: v1(70.23,50.19) 69.83,49.8 U14.H9
  BOTTOM w0.381: C243.1 v4(78.19,52.1) ; C243.1 R95.2 ; C243.1 C240.1
